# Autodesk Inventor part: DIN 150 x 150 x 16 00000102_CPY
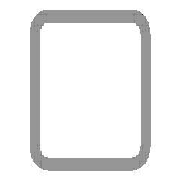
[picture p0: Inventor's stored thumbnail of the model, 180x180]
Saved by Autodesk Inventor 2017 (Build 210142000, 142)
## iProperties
Created: 2017-11
Part Number: DIN 150 x 150 x 16 00000102_CPY
Material: Steel, Mild
Description: Cold formed welded structural hollow sections of non-alloy and fine grain structural steel
Document SubType Name: Modeling
Standard: DIN
Designer: iusti
Standard Revision: 2006-07
Standards Organization: DIN
Language: en-US
Size Designation: 150 x 150 x 16
Categories: <MemberInstance><Categories><Category DisplayName="Structural Shapes" InternalName="089c4875-fa83-4c05-b084-43b9cc11f5ed" Mnemonic="GRDR"><CategoryParameter Dis
Stock Number: 150 x 150 x 16
Mass: 90369.3 g
Surface Area: 14539.6 cm^2
Volume: 11512 cm^3
Density: 7.85 g/cm^3
Appearance: Semi-Polished
IsCustomPart: 1
G_W: 150.000 mm
G_H: 150.000 mm
G_L: 1539.608 mm
+A2D54500-A6BB-4D6E-934F-4456235B9375+CUTDETAIL2: Cut
_CCFamilyMember: 76
_CCFamilyDisplayName: DIN EN 10219-2 (Square Hollow Section - Cold Formed) - Cold formed welded structural hollow sections of non-alloy and fine grain structural steel
_FrameMemberDoc: Frame Member File
_Version: 15.0.0
_GetPNFromCC: 1
Author: iusti
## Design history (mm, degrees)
node "Start plane"
node "End plane"
sketch "Sketch"
  geometry: L1 (-75, -27)-(-75, 27); L2 (-27, 75)-(27, 75); L3 (75, 27)-(75, -27); L4 (27, -75)-(-27, -75); L5 (-27, 59)-(27, 59); L6 (59, 27)-(59, -27); L7 (27, -59)-(-27, -59); L8 (-59, -27)-(-59, 27); L9 (0, 118.918)-(0, -118.918) reference; L10 (-118.918, 0)-(118.918, 0) reference; A1 r 48 centre (-27, -27) between (-75, -27) and (-27, -75); A2 r 48 centre (-27, 27) between (-27, 75) and (-75, 27); A3 r 48 centre (27, 27) between (75, 27) and (27, 75); A4 r 48 centre (27, -27) between (27, -75) and (75, -27); A5 r 32 centre (-27, 27) between (-27, 59) and (-59, 27); A6 r 32 centre (27, 27) between (59, 27) and (27, 59); A7 r 32 centre (27, -27) between (27, -59) and (59, -27); A8 r 32 centre (-27, -27) between (-59, -27) and (-27, -59)
  constraints: 16 end point, 16 point on circle, 8 centre point, 8 tangent, 4 parallel, 3 equal radius, 2 perpendicular, 7 other
  dimensions: "d7" = 48 radius of A1 (= G_IR); "d10" = 150 distance between parallel lines of L2 L4 (= G_H); "d11" = 150 distance between parallel lines of L1 L3 (= G_W); "d12" = 16 distance between parallel lines of L3 L6 (= G_T); "d15" = 75 distance between parallel lines of L2 L10 (= 0.5 x d10); "d16" = 75 distance between parallel lines of L9 L3 (= 0.5 x d11)
extrude "Body" new body sketch "Sketch" stored distance "d3" = 1539.60835 (= G_L); taper "d4" = 0 deg
node "Driven Length"
  sketch "Sketch3"
    geometry: L1 (0, 0)-(10, 0) reference
    constraints: 2 end point, 1 horizontal
  workplane "Work Plane3"
  sketch "Sketch4"
    geometry: L1 (-2, 0)-(12, 0) reference; L2 (-2, 1539.608)-(12, 1539.608) reference
    dimensions: "d18" = 1539.60835 distance between parallel lines of L1 L2 (derived)
workplane "Work Plane5"
split "Split2"
body "Solid1"
other parameters: "G_W" = 150 [user parameter; used in 1 equation term], "G_H" = 150 [user parameter; used in 1 equation term], "G_T" = 16 [user parameter; used in 1 equation term], "G_IR" = 48 [user parameter; used in 1 equation term], "G_L" = 1539.60835 (= d18) [user parameter; used in 1 equation term], "G_OFFSET_START" = 0 [user parameter; used in 1 equation term], "G_OFFSET_END" = -75 [user parameter; used in 1 equation term], "d13" = 0 (computed from G_OFFSET_START), "d14" = 1539.60835 (= G_OFFSET_END + B_L), "B_L" = 1614.60835 [user parameter; used in 1 equation term], "d17" = 90 deg
